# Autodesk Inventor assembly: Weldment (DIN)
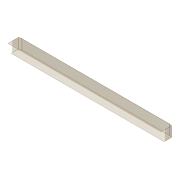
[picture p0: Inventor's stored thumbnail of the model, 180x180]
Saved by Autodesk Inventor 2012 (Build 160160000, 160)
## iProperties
Length Units: 11269
Angle Units: 11283
Time Units: 11279
Mass Units: 11290
Length Display Precision: 3
Angle Display Precision: 2
Part Number: Weldment (DIN)
Document SubType Name: Weldment
Created: 2002-06
Designer: smithga
Shininess: 64.0
Angle Units: 11279
Time Units: 11290
Mass Units: 11283
Compacted: True
Company: CAD-Verlag
Part Number: schutz_140_3-4
Created: 2004-09
Designer: Greiling
Material: Geschweißtes Aluminum-6061
Manufacturer: Standard
Standards Organization: Custom
Weld Material: Geschweißtes Aluminum-6061
Density: 0.0
Volumn: 0.0
Area: 0.0
PropertySet Name: Model Information
Control State: 0
Master: False
Author: Jürgen Kronas
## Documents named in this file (3)
- C:\DemoDaten2012\CAD Daten\Daten Vault 2012 Inventor\Kapitel 6\6.4\Rollenbahn\Rollenbahn 1400\schutz_140_3-4.iam
- C:\DemoDaten2012\CAD Daten\Daten Vault 2012 Inventor\Kapitel 6\6.4\Rollenbahn\Rollenbahn 1400\schutz_140_3-4_1.ipt
- C:\DemoDaten2012\CAD Daten\Daten Vault 2012 Inventor\Kapitel 6\6.4\Rollenbahn\Rollenbahn 1400\schutz_140_3-4_2.ipt
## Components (3 placed, 2 different names)
1. schutz_140_3-4_1:1 — Passend:1, Passend:2, Passend:3, Passend:4, Fluchtend:1, Passend:5
2. schutz_140_3-4_2:1 — Passend:1, Passend:2, Passend:3
3. schutz_140_3-4_2:2 — Passend:4, Fluchtend:1, Passend:5
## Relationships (6: Mate 5, Flush 1)
- Passend:1 [Mate]: schutz_140_3-4_1:1 ↔ schutz_140_3-4_2:1
- Passend:2 [Mate]: schutz_140_3-4_1:1 ↔ schutz_140_3-4_2:1
- Passend:3 [Mate]: schutz_140_3-4_1:1 ↔ schutz_140_3-4_2:1
- Passend:4 [Mate]: schutz_140_3-4_1:1 ↔ schutz_140_3-4_2:2
- Fluchtend:1 [Flush]: schutz_140_3-4_1:1 ↔ schutz_140_3-4_2:2
- Passend:5 [Mate]: schutz_140_3-4_1:1 ↔ schutz_140_3-4_2:2
